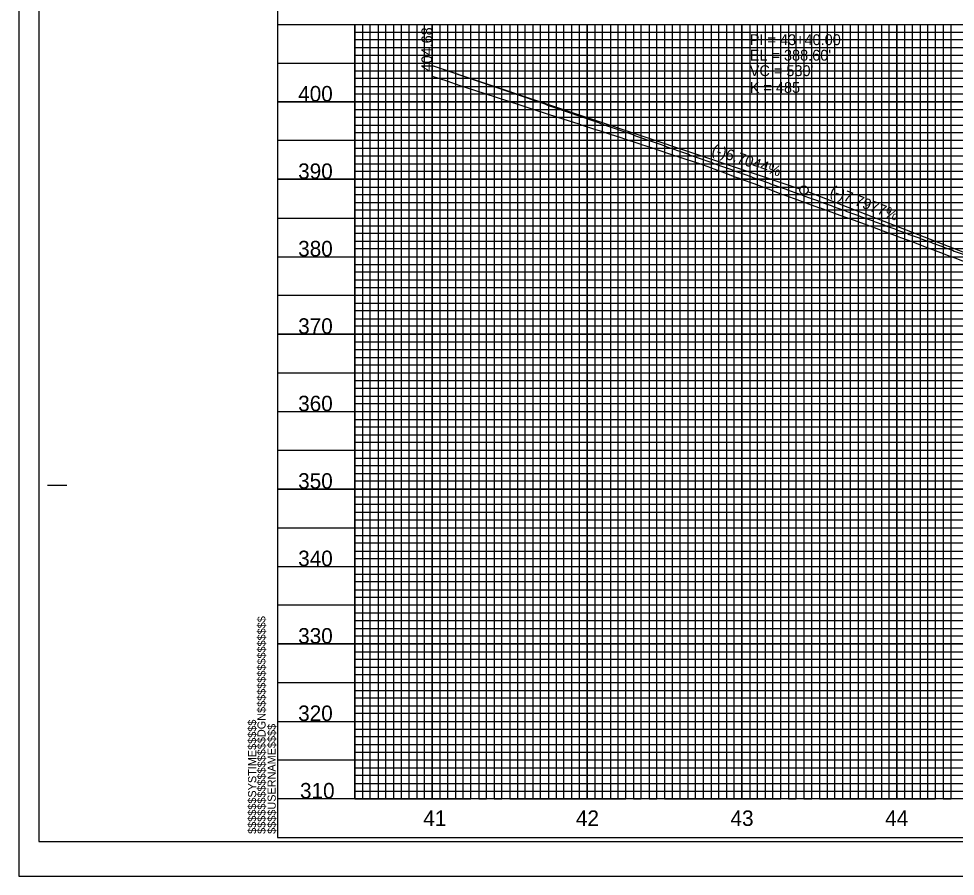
# Model space of a CAD drawing. Extents: x 571503 to 593215, y -77195 to -51828.
# Drawn here: x 582330 to 582935, y -74015 to -73461 of the extents above; entities that cross this region are included whole.
import ezdxf

# ---------------------------------------------------------------- set-up
doc = ezdxf.new("R2010")
doc.units = 0
for name, color, linetype in [('Exist Vertical Profile Ground Line', 7, 'Continuous'), ('Exist Vertical Profile Horizontal Axis Label Major', 7, 'Continuous'), ('Exist Vertical Profile Vertical Axis Label', 7, 'Continuous'), ('Prop Vertical Profile Curve Label', 7, 'Continuous'), ('Prop Vertical Profile Grade', 7, 'Continuous'), ('Prop Vertical Profile Grade Label', 7, 'Continuous'), ('Prop VPI Label', 7, 'Continuous'), ('Sheet Cutting Line CELL', 7, 'Continuous'), ('Sheet DOT Grid CELL', 7, 'Continuous'), ('Sheet Layout Profile Border Port 2', 7, 'Continuous'), ('Sheet Plot Border Inside CELL', 7, 'Continuous'), ('Sheet Plot Border Outside CELL', 7, 'Continuous'), ('Sheet Profile CELL', 7, 'Continuous'), ('Sheet Profile Grid Major CELL', 7, 'Continuous'), ('Sheet Profile Grid Middle CELL', 7, 'Continuous'), ('Sheet Profile Grid Minor CELL', 7, 'Continuous')]:
    doc.layers.add(name, color=color, linetype=linetype)

msp = doc.modelspace()

# ---------------------------------------------------------------- linework, layer by layer
at = {"layer": 'Exist Vertical Profile Ground Line'}
msp.add_lwpolyline([(582596.98, -73498.45), (582606.35, -73501.53), (582614.89, -73504.46), (582630.25, -73509.51), (582646.83, -73514.89), (582653.62, -73517.09), (582662.48, -73519.97), (582677.81, -73524.94), (582691.55, -73529.34), (582693.23, -73529.88), (582702.5, -73532.88), (582704.72, -73533.59), (582711.78, -73535.89), (582718.77, -73538.16), (582721.05, -73538.92), (582730.33, -73541.98), (582731.49, -73542.36), (582739.61, -73545.06), (582744.66, -73546.74), (582748.88, -73548.14), (582749.5, -73548.35), (582758.16, -73551.2), (582767.43, -73554.26), (582769.63, -73554.98), (582776.71, -73557.56), (582778.9, -73558.36), (582785.98, -73561), (582793.05, -73563.63), (582795.26, -73564.43), (582797.19, -73565.13), (582804.54, -73567.87), (582813.81, -73571.33), (582823.09, -73574.8), (582824.11, -73575.18), (582824.74, -73575.42), (582825.25, -73575.61), (582832.36, -73578.17), (582841.64, -73581.5), (582846.97, -73583.42), (582847.43, -73583.59), (582850.91, -73584.84), (582860.19, -73588.18), (582869.47, -73591.52), (582878.35, -73594.72), (582878.74, -73594.86), (582879.6, -73595.17), (582888.02, -73598.34), (582897.29, -73601.84), (582899.44, -73602.65), (582900.05, -73602.87), (582906.57, -73605.33), (582915.84, -73608.83), (582925.12, -73612.34), (582931.26, -73614.66), (582931.73, -73614.84), (582934.4, -73615.87), (582943.67, -73619.46)], dxfattribs=at)
at = {"layer": 'Prop Vertical Profile Grade'}
msp.add_spline([(582596.98, -73491.67), (582607.08, -73495.09), (582617.18, -73498.52), (582627.28, -73501.96), (582637.38, -73505.41), (582647.48, -73508.86), (582657.58, -73512.33), (582667.68, -73515.81), (582677.78, -73519.3), (582687.88, -73522.81), (582697.98, -73526.32), (582708.08, -73529.84), (582718.18, -73533.37), (582728.28, -73536.92), (582738.38, -73540.47), (582748.48, -73544.03), (582758.58, -73547.61), (582768.68, -73551.19), (582778.78, -73554.79), (582788.88, -73558.4), (582798.98, -73562.01), (582809.08, -73565.64), (582819.18, -73569.28), (582829.28, -73572.93), (582839.38, -73576.59), (582849.48, -73580.26), (582859.58, -73583.94), (582869.68, -73587.63), (582879.78, -73591.33), (582889.88, -73595.04), (582899.98, -73598.76), (582910.08, -73602.49), (582920.18, -73606.24), (582930.28, -73609.99), (582940.38, -73613.76), (582950.48, -73617.53), (582960.58, -73621.32), (582970.68, -73625.11), (582980.78, -73628.92), (582990.88, -73632.73), (583000.98, -73636.56), (583011.08, -73640.4), (583021.18, -73644.25), (583031.28, -73648.11), (583041.38, -73651.98), (583051.48, -73655.86), (583061.58, -73659.75), (583071.68, -73663.65), (583081.78, -73667.56), (583091.88, -73671.48), (583101.98, -73675.41)], degree=3, dxfattribs=at)
at = {"layer": 'Prop VPI Label'}
for p, q in [((582596.98, -73491.64), (582834.38, -73571.22)), ((583101.98, -73675.41), (582839.55, -73573.09))]:
    msp.add_line(p, q, dxfattribs=at)
msp.add_circle((582836.98, -73572.09), 2.75, dxfattribs=at)
at = {"layer": 'Sheet Cutting Line CELL'}
for p, q in [((582329.98, -72915.09), (582329.98, -74015.09)), ((582329.98, -74015.09), (584013.98, -74015.09))]:
    msp.add_line(p, q, dxfattribs=at)
at = {"layer": 'Sheet DOT Grid CELL'}
for p, q in [((582496.98, -73465.09), (583996.87, -73465.09)), ((582546.98, -73465.09), (582546.98, -73965.09)), ((582596.98, -73465.09), (582596.98, -73965.09)), ((582646.98, -73465.09), (582646.98, -73965.09)), ((582696.98, -73465.09), (582696.98, -73965.09)), ((582746.98, -73465.09), (582746.98, -73965.09)), ((582796.98, -73465.09), (582796.98, -73965.09)), ((582846.98, -73465.09), (582846.98, -73965.09)), ((582896.98, -73465.09), (582896.98, -73965.09)), ((582496.98, -73515.09), (583996.87, -73515.09)), ((582496.98, -73565.09), (583996.87, -73565.09)), ((582496.98, -73615.09), (583996.87, -73615.09)), ((582496.98, -73665.09), (583996.87, -73665.09)), ((582496.98, -73715.09), (583996.87, -73715.09)), ((582496.98, -73765.09), (583996.87, -73765.09)), ((582496.98, -73815.09), (583996.87, -73815.09)), ((582496.98, -73865.09), (583996.87, -73865.09)), ((582496.98, -73915.09), (583996.87, -73915.09))]:
    msp.add_line(p, q, dxfattribs=at)
at = {"layer": 'Sheet Layout Profile Border Port 2'}
msp.add_lwpolyline([(582546.98, -73465.09), (583946.98, -73465.09), (583946.98, -73965.09), (582546.98, -73965.09)], close=True, dxfattribs=at)
at = {"layer": 'Sheet Plot Border Inside CELL'}
msp.add_lwpolyline([(582342.98, -73992.64), (584009.48, -73992.64), (584009.48, -72937.54), (582342.98, -72937.54)], close=True, dxfattribs=at)
at = {"layer": 'Sheet Plot Border Outside CELL'}
msp.add_lwpolyline([(582329.98, -74015.09), (584013.98, -74015.09), (584013.98, -72915.09), (582329.98, -72915.09)], close=True, dxfattribs=at)
at = {"layer": 'Sheet Profile CELL'}
for p, q in [((582496.98, -73465.09), (583996.98, -73465.09)), ((582348.48, -73762.59), (582360.98, -73762.59)), ((583996.98, -73965.09), (582496.98, -73965.09)), ((582496.98, -73990.09), (583996.98, -73990.09)), ((582496.98, -73990.09), (582496.98, -73990.09)), ((582496.98, -73990.09), (582496.98, -73990.09)), ((582496.98, -73990.09), (582496.98, -73990.09)), ((582496.98, -73990.09), (582496.98, -73990.09)), ((582496.98, -73990.09), (582496.98, -73990.09)), ((582496.98, -73990.09), (582496.98, -73990.09)), ((582496.98, -73990.09), (582496.98, -73990.09))]:
    msp.add_line(p, q, dxfattribs=at)
msp.add_lwpolyline([(583996.98, -72940.09), (582496.98, -72940.09), (582496.98, -73990.09), (583996.98, -73990.09)], close=True, dxfattribs=at)
msp.add_lwpolyline([(582534.48, -73990.09), (582534.48, -73990.09)], dxfattribs=at)
at = {"layer": 'Sheet Profile Grid Major CELL'}
msp.add_line((582496.98, -73965.09), (582496.98, -73965.09), dxfattribs=at)
for points in [[(582546.98, -73465.09), (582546.98, -73965.09), (582596.98, -73965.09), (582596.98, -73465.09), (582646.98, -73465.09), (582646.98, -73965.09), (582696.98, -73965.09), (582696.98, -73465.09), (582746.98, -73465.09), (582746.98, -73965.09), (582796.98, -73965.09), (582796.98, -73465.09), (582846.98, -73465.09), (582846.98, -73965.09), (582896.98, -73965.09), (582896.98, -73465.09), (582946.98, -73465.09)], [(583996.98, -73515.09), (582496.98, -73515.09)], [(583996.98, -73565.09), (582496.98, -73565.09), (582496.98, -73615.09), (583996.98, -73615.09)], [(583996.98, -73665.09), (582496.98, -73665.09), (582496.98, -73715.09), (583996.98, -73715.09)], [(583996.98, -73765.09), (582496.98, -73765.09), (582496.98, -73815.09), (583996.98, -73815.09)], [(583996.98, -73865.09), (582496.98, -73865.09), (582496.98, -73865.09), (582496.98, -73915.09), (583996.98, -73915.09)], [(583996.98, -73965.09), (582496.98, -73965.09)]]:
    msp.add_lwpolyline(points, dxfattribs=at)
at = {"layer": 'Sheet Profile Grid Middle CELL'}
for points in [[(582521.98, -73465.09), (582571.98, -73465.09), (582571.98, -73965.09), (582621.98, -73965.09), (582621.98, -73465.09), (582671.98, -73465.09), (582671.98, -73965.09), (582721.98, -73965.09), (582721.98, -73465.09), (582771.98, -73465.09), (582771.98, -73965.09), (582821.98, -73965.09), (582821.98, -73465.09), (582871.98, -73465.09), (582871.98, -73965.09), (582921.98, -73965.09), (582921.98, -73465.09), (582971.98, -73465.09)], [(582496.98, -73490.09), (583996.98, -73490.09)], [(583996.98, -73540.09), (582496.98, -73540.09), (582496.98, -73590.09), (583996.98, -73590.09)], [(583996.98, -73640.09), (582496.98, -73640.09), (582496.98, -73690.09), (583996.98, -73690.09)], [(583996.98, -73740.09), (582496.98, -73740.09), (582496.98, -73790.09), (583996.98, -73790.09)], [(583996.98, -73840.09), (582496.98, -73840.09), (582496.98, -73890.09), (583996.98, -73890.09)], [(583996.98, -73940.09), (582496.98, -73940.09)]]:
    msp.add_lwpolyline(points, dxfattribs=at)
at = {"layer": 'Sheet Profile Grid Minor CELL'}
for p, q in [((582546.98, -73470.09), (583946.98, -73470.09)), ((583946.98, -73475.09), (582546.98, -73475.09)), ((582546.98, -73480.09), (583946.98, -73480.09)), ((583946.98, -73485.09), (582546.98, -73485.09)), ((582546.98, -73495.09), (583946.98, -73495.09)), ((583946.98, -73500.09), (582546.98, -73500.09)), ((582546.98, -73505.09), (583946.98, -73505.09)), ((583946.98, -73510.09), (582546.98, -73510.09)), ((582546.98, -73520.09), (583946.98, -73520.09)), ((583946.98, -73525.09), (582546.98, -73525.09)), ((582546.98, -73530.09), (583946.98, -73530.09)), ((583946.98, -73535.09), (582546.98, -73535.09)), ((582546.98, -73545.09), (583946.98, -73545.09)), ((583946.98, -73550.09), (582546.98, -73550.09)), ((582546.98, -73555.09), (583946.98, -73555.09)), ((583946.98, -73560.09), (582546.98, -73560.09)), ((582546.98, -73570.09), (583946.98, -73570.09)), ((583946.98, -73575.09), (582546.98, -73575.09)), ((582546.98, -73580.09), (583946.98, -73580.09)), ((583946.98, -73585.09), (582546.98, -73585.09)), ((582546.98, -73595.09), (583946.98, -73595.09)), ((583946.98, -73600.09), (582546.98, -73600.09)), ((582546.98, -73605.09), (583946.98, -73605.09)), ((583946.98, -73610.09), (582546.98, -73610.09)), ((582546.98, -73620.09), (583946.98, -73620.09)), ((583946.98, -73625.09), (582546.98, -73625.09)), ((582546.98, -73630.09), (583946.98, -73630.09)), ((583946.98, -73635.09), (582546.98, -73635.09)), ((582546.98, -73645.09), (583946.98, -73645.09)), ((583946.98, -73650.09), (582546.98, -73650.09)), ((582546.98, -73655.09), (583946.98, -73655.09)), ((583946.98, -73660.09), (582546.98, -73659.94)), ((582546.98, -73670.09), (583946.98, -73670.09)), ((583946.98, -73675.09), (582546.98, -73675.09)), ((582546.98, -73680.09), (583946.98, -73680.09)), ((583946.98, -73685.09), (582546.98, -73685.09)), ((582546.98, -73695.09), (583946.98, -73695.09)), ((583946.98, -73700.09), (582546.98, -73700.09)), ((582546.98, -73705.09), (583946.98, -73705.09)), ((583946.98, -73710.09), (582546.98, -73710.09)), ((582546.98, -73720.09), (583946.98, -73720.09)), ((583946.98, -73725.09), (582546.98, -73725.09)), ((582546.98, -73730.09), (583946.98, -73730.09)), ((583946.98, -73735.09), (582546.98, -73735.09)), ((582546.98, -73745.09), (583946.98, -73745.09)), ((583946.98, -73750.09), (582546.98, -73750.09)), ((582546.98, -73755.09), (583946.98, -73755.09)), ((583946.98, -73760.09), (582546.98, -73760.09)), ((582546.98, -73770.09), (583946.98, -73770.09)), ((583946.98, -73775.09), (582546.98, -73775.09)), ((582546.98, -73780.09), (583946.98, -73780.09)), ((583946.98, -73785.09), (582546.98, -73785.09)), ((582546.98, -73795.09), (583946.98, -73795.09)), ((583946.98, -73800.09), (582546.98, -73800.09)), ((582546.98, -73805.09), (583946.98, -73805.09)), ((583946.98, -73810.09), (582546.98, -73810.09)), ((582546.98, -73820.09), (583946.98, -73820.09)), ((583946.98, -73825.09), (582546.98, -73825.09)), ((582546.98, -73830.09), (583946.98, -73830.09)), ((583946.98, -73835.09), (582546.98, -73835.09)), ((582546.98, -73845.09), (583946.98, -73845.09)), ((583946.98, -73850.09), (582546.98, -73850.09)), ((582546.98, -73855.09), (583946.98, -73855.09)), ((583946.98, -73860.09), (582546.98, -73860.09)), ((582546.98, -73870.09), (583946.98, -73870.09)), ((583946.98, -73875.09), (582546.98, -73875.09)), ((582546.98, -73880.09), (583946.98, -73880.09)), ((583946.98, -73885.09), (582546.98, -73885.09)), ((582546.98, -73895.09), (583946.98, -73895.09)), ((583946.98, -73900.09), (582546.98, -73900.09)), ((582546.98, -73905.09), (583946.98, -73905.09)), ((583946.98, -73910.09), (582546.98, -73910.09)), ((582546.98, -73920.09), (583946.98, -73920.09)), ((583946.98, -73925.09), (582546.98, -73925.09)), ((582546.98, -73930.09), (583946.98, -73930.09)), ((583946.98, -73935.09), (582546.98, -73935.09)), ((582546.98, -73945.09), (583946.98, -73945.09)), ((583946.98, -73950.09), (582546.98, -73950.09)), ((582546.98, -73955.09), (583946.98, -73955.09)), ((582546.98, -73960.09), (583946.98, -73960.09))]:
    msp.add_line(p, q, dxfattribs=at)
for points in [[(582546.98, -73465.09), (582551.98, -73465.09), (582551.98, -73965.09), (582556.98, -73965.09), (582556.98, -73465.09), (582561.98, -73465.09), (582561.98, -73965.09), (582566.98, -73965.09), (582566.98, -73465.09), (582576.98, -73465.09), (582576.98, -73965.09), (582581.98, -73965.09), (582581.98, -73465.09), (582586.98, -73465.09), (582586.98, -73965.09), (582591.98, -73965.09), (582601.98, -73965.09), (582606.98, -73965.09), (582606.98, -73465.09), (582611.98, -73465.09), (582611.98, -73965.09), (582616.98, -73965.09), (582616.98, -73465.09), (582626.98, -73465.09), (582626.98, -73965.09), (582631.98, -73965.09), (582631.98, -73465.09), (582636.98, -73465.09), (582636.98, -73965.09), (582641.98, -73965.09), (582641.98, -73465.09), (582651.98, -73465.09), (582651.98, -73965.09), (582656.98, -73965.09), (582656.98, -73465.09), (582661.98, -73465.09), (582661.98, -73965.09), (582666.98, -73965.09), (582666.98, -73465.09), (582676.98, -73465.09), (582676.98, -73965.09), (582681.98, -73965.09), (582681.98, -73465.09), (582686.98, -73465.09), (582686.98, -73965.09), (582691.98, -73965.09), (582691.98, -73465.09), (582701.98, -73465.09), (582701.98, -73965.09), (582706.98, -73965.09), (582706.98, -73465.09), (582711.98, -73465.09), (582711.98, -73965.09), (582716.98, -73965.09), (582716.98, -73465.09), (582726.98, -73465.09), (582726.98, -73965.09), (582731.98, -73965.09), (582731.98, -73465.09), (582736.98, -73465.09), (582736.98, -73965.09), (582741.98, -73965.09), (582741.98, -73465.09), (582751.98, -73465.09), (582751.98, -73965.09), (582756.98, -73965.09), (582756.98, -73465.09), (582761.98, -73465.09), (582761.98, -73965.09)], [(582591.98, -73965.09), (582591.98, -73465.09), (582601.98, -73465.09), (582601.98, -73965.09)], [(582761.98, -73965.09), (582766.98, -73965.09), (582766.98, -73465.09), (582776.98, -73465.09), (582776.98, -73965.09), (582781.98, -73965.09), (582781.98, -73465.09), (582786.98, -73465.09), (582786.98, -73965.09), (582791.98, -73965.09), (582791.98, -73465.09), (582801.98, -73465.09), (582801.98, -73965.09), (582806.98, -73965.09), (582806.98, -73465.09), (582811.98, -73465.09), (582811.98, -73965.09), (582816.98, -73965.09), (582816.98, -73465.09), (582826.98, -73465.09), (582826.98, -73965.09), (582831.98, -73965.09), (582831.98, -73465.09), (582836.98, -73465.09), (582836.98, -73965.09), (582841.98, -73965.09), (582841.98, -73465.09), (582851.98, -73465.09), (582851.98, -73965.09), (582856.98, -73965.09), (582856.98, -73465.09), (582861.98, -73465.09), (582861.98, -73965.09), (582866.98, -73965.09), (582866.98, -73465.09), (582876.98, -73465.09), (582876.98, -73965.09), (582881.98, -73965.09), (582881.98, -73465.09), (582886.98, -73465.09), (582886.98, -73965.09), (582891.98, -73965.09), (582891.98, -73465.09), (582901.98, -73465.09), (582901.98, -73965.09), (582906.98, -73965.09), (582906.98, -73465.09), (582911.98, -73465.09), (582911.98, -73965.09), (582916.98, -73965.09), (582916.98, -73465.09), (582926.98, -73465.09), (582926.98, -73965.09), (582931.98, -73965.09), (582931.98, -73465.09), (582936.98, -73465.09)]]:
    msp.add_lwpolyline(points, dxfattribs=at)

# ---------------------------------------------------------------- texts
at = {"layer": 'Exist Vertical Profile Horizontal Axis Label Major'}
for s, p in [('41', (582591.21, -73982.59)), ('42', (582689.76, -73982.59)), ('43', (582789.59, -73982.59)), ('44', (582889.44, -73982.59))]:
    msp.add_text(s, height=10, dxfattribs=at).set_placement(p)
at = {"layer": 'Exist Vertical Profile Vertical Axis Label'}
for s, p in [('400', (582510.42, -73514.84)), ('390', (582510.42, -73564.84)), ('380', (582510.42, -73614.84)), ('370', (582510.42, -73664.84)), ('360', (582510.42, -73714.84)), ('350', (582510.42, -73764.84)), ('340', (582510.42, -73814.84)), ('330', (582510.42, -73864.84)), ('320', (582510.42, -73914.84)), ('310', (582511.61, -73964.84))]:
    msp.add_text(s, height=10, dxfattribs=at).set_placement(p)
at = {"layer": 'Prop Vertical Profile Curve Label'}
for s, p in [("VC = 530'", (582801.98, -73498.46)), ('K = 485', (582801.98, -73509.29))]:
    msp.add_text(s, height=7, dxfattribs=at).set_placement(p)
at = {"layer": 'Prop Vertical Profile Grade Label'}
for s, rotation, p in [('(-)6.7044%', 341.46781, (582776.92, -73548.79)), ('(-)7.7977%', 338.69987, (582853.21, -73575.2))]:
    msp.add_text(s, height=7, rotation=rotation, dxfattribs=at).set_placement(p)
at = {"layer": 'Prop VPI Label'}
msp.add_text('404.68', height=7, rotation=90, dxfattribs=at).set_placement((582596.98, -73495.54))
for s, p in [('PI = 43+40.00', (582801.98, -73478.46)), ("EL = 388.60'", (582801.98, -73488.46))]:
    msp.add_text(s, height=7, dxfattribs=at).set_placement(p)
at = {"layer": 'Sheet Profile CELL'}
for s, p in [('$$$$$$$$$$$$$$$$DGN$$$$$$$$$$$$$$$$', (582489.35, -73987.72)), ('$$$$$$SYSTIME$$$$$', (582483.3, -73987.72)), ('$$$$USERNAME$$$$', (582495.92, -73987.71))]:
    msp.add_text(s, height=5.25, rotation=90, dxfattribs=at).set_placement(p)

doc.saveas('drawing.dxf')
